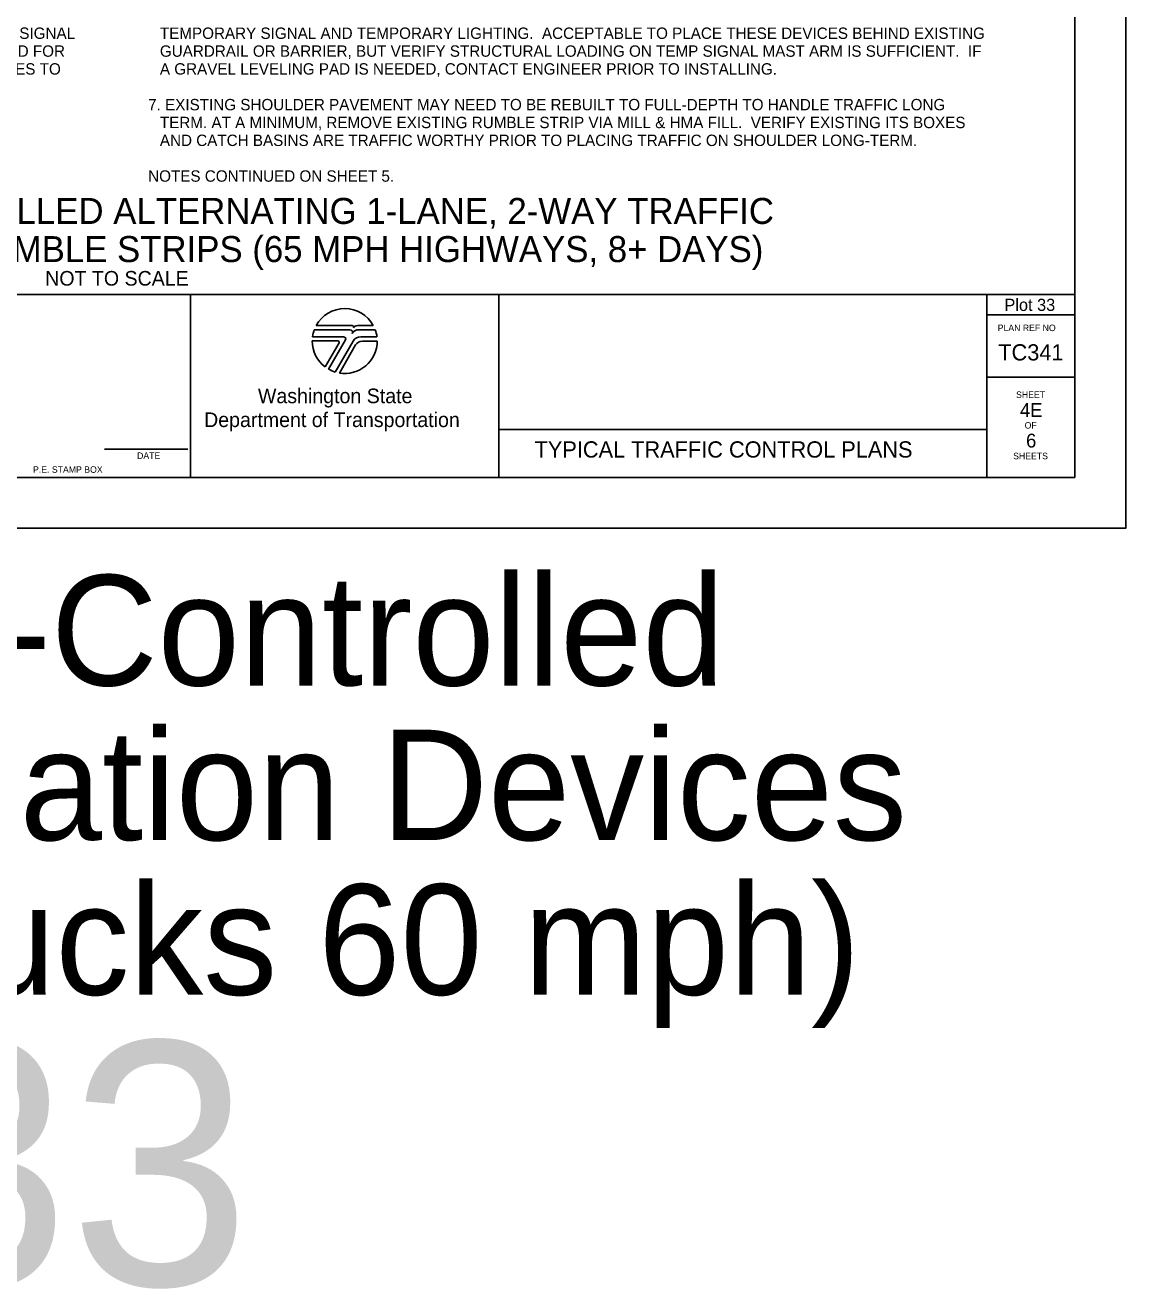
# Model space of a CAD drawing. Extents: x 99977 to 100176, y 99905 to 100011.
# Drawn here: x 100049.29 to 100056.06, y 99905.01 to 99912.78 of the extents above; entities that cross this region are included whole.
import ezdxf

# ---------------------------------------------------------------- set-up
doc = ezdxf.new("R2010")
doc.units = 0
for name, color, linetype in [('SH_DE_DetailHeading1Text', 7, 'Continuous'), ('SH_GI_GeneralNotesBodyText', 7, 'Continuous'), ('SH_GI_PlotLimits', 7, 'Continuous'), ('SH_GI_SheetBorder', 7, 'Continuous'), ('SH_GI_SheetLocationText', 7, 'Continuous'), ('SH_GI_SheetTextInCells', 7, 'Continuous'), ('SH_GI_TitleBlockText', 7, 'Continuous'), ('SH_GI_WSDOTLogo', 7, 'Continuous')]:
    doc.layers.add(name, color=color, linetype=linetype)

msp = doc.modelspace()

# ---------------------------------------------------------------- linework, layer by layer
at = {"layer": 'SH_GI_PlotLimits'}
msp.add_lwpolyline([(100039.0625, 99909.6875), (100056.0625, 99909.6875), (100056.0625, 99920.6875), (100039.0625, 99920.6875)], close=True, dxfattribs=at)
at = {"layer": 'SH_GI_SheetBorder'}
for p, q in [((100055.75, 99920.375), (100055.75, 99910)), ((100040, 99911.1259), (100055.75, 99911.1259)), ((100050.3089, 99911.1259), (100050.3089, 99910)), ((100052.2055, 99911.1259), (100052.2055, 99910)), ((100055.2079, 99911.1259), (100055.2079, 99910)), ((100055.2079, 99911.0008), (100055.75, 99911.0008)), ((100055.2079, 99910.6176), (100055.75, 99910.6176)), ((100052.2055, 99910.2955), (100055.2079, 99910.2955)), ((100049.7797, 99910.1733), (100050.2914, 99910.1733)), ((100040, 99910), (100055.75, 99910))]:
    msp.add_line(p, q, dxfattribs=at)
at = {"layer": 'SH_GI_WSDOTLogo'}
for p, q in [((100051.303, 99910.9354), (100051.0815, 99910.9354)), ((100051.433, 99910.9354), (100051.3351, 99910.9354)), ((100051.0572, 99910.84), (100051.2148, 99910.84)), ((100051.059, 99910.8661), (100051.2496, 99910.8661)), ((100051.2894, 99910.9094), (100051.0697, 99910.9094)), ((100051.261, 99910.8464), (100051.1567, 99910.6672)), ((100051.1989, 99910.6487), (100051.3089, 99910.839)), ((100051.343, 99910.9094), (100051.3429, 99910.9094)), ((100051.4448, 99910.9094), (100051.343, 99910.9094)), ((100051.3558, 99910.8661), (100051.4555, 99910.8661)), ((100051.3655, 99910.8394), (100051.4572, 99910.8394)), ((100051.222, 99910.8277), (100051.1364, 99910.6807)), ((100051.2244, 99910.6428), (100051.3242, 99910.8156))]:
    msp.add_line(p, q, dxfattribs=at)
for centre, radius, start, end in [((100051.2572, 99910.84), 0.2, 28.47865, 151.53204), ((100051.303, 99910.9263), 0.00903, 329.87418, 90.00328), ((100051.3352, 99910.9066), 0.0287, 90.00721, 148.16763), ((100051.2572, 99910.84), 0.2, 179.99864, 232.84327), ((100051.2572, 99910.84), 0.2, 159.69598, 172.50569), ((100051.2149, 99910.8318), 0.0082, 329.74356, 90), ((100051.2572, 99910.84), 0.2, 260.54554, 359.80857), ((100051.2497, 99910.853), 0.0131, 329.76834, 90), ((100051.2894, 99910.8946), 0.0148, 327.8418, 89.99855), ((100051.3429, 99910.861), 0.0484, 89.99529, 147.82376), ((100051.3558, 99910.8119), 0.0542, 90, 149.99738), ((100051.3654, 99910.7918), 0.0476, 90, 150.05432), ((100051.2572, 99910.84), 0.2, 7.49431, 20.29406), ((100051.2572, 99910.84), 0.2, 239.79292, 253.0448)]:
    msp.add_arc(centre, radius, start, end, dxfattribs=at)

# ---------------------------------------------------------------- texts
at = {"layer": 'SH_DE_DetailHeading1Text'}
for s, height, p in [('SIMPLE TEMPORARY SIGNAL-CONTROLLED ALTERNATING 1-LANE, 2-WAY TRAFFIC', 0.16, (100045.196, 99911.5606)), ('25 WZSL + CHANNELIZING DEVICES + RUMBLE STRIPS (65 MPH HIGHWAYS, 8+ DAYS)', 0.16, (100044.9338, 99911.3259)), ('NOT TO SCALE', 0.09, (100049.4141, 99911.1809))]:
    msp.add_text(s, height=height, rotation=360, dxfattribs=at).set_placement(p)
at = {"layer": 'SH_GI_GeneralNotesBodyText'}
for s, p in [(' THIS SIGNAL ', (100048.9894, 99912.6998)), ('TEMPORARY SIGNAL AND TEMPORARY LIGHTING.  ACCEPTABLE TO PLACE THESE DEVICES BEHIND EXISTING ', (100050.1197, 99912.6998)), ('  THE SIGNAL IS TIMED FOR ', (100048.272, 99912.5899)), ('GUARDRAIL OR BARRIER, BUT VERIFY STRUCTURAL LOADING ON TEMP SIGNAL MAST ARM IS SUFFICIENT.  IF ', (100050.1197, 99912.5899)), (' TO ALLOW BICYCLES TO ', (100048.3553, 99912.48)), ('A GRAVEL LEVELING PAD IS NEEDED, CONTACT ENGINEER PRIOR TO INSTALLING.', (100050.1197, 99912.48)), ('7. EXISTING SHOULDER PAVEMENT MAY NEED TO BE REBUILT TO FULL-DEPTH TO HANDLE TRAFFIC LONG ', (100050.0475, 99912.2602)), ('TERM. AT A MINIMUM, REMOVE EXISTING RUMBLE STRIP VIA MILL & HMA FILL.  VERIFY EXISTING ITS BOXES ', (100050.1197, 99912.1503)), ('AND CATCH BASINS ARE TRAFFIC WORTHY PRIOR TO PLACING TRAFFIC ON SHOULDER LONG-TERM.', (100050.1197, 99912.0404)), ('NOTES CONTINUED ON SHEET 5.', (100050.0475, 99911.8206))]:
    msp.add_text(s, height=0.07, rotation=360, dxfattribs=at).set_placement(p)
at = {"layer": 'SH_GI_SheetBorder'}
msp.add_text('PLAN REF NO', height=0.040032, dxfattribs=at).set_placement((100055.2747, 99910.9008))
at = {"layer": 'SH_GI_SheetLocationText'}
for s, height, p in [('Plot 33', 0.075, (100055.3164, 99911.025)), (' Temp Signal-Controlled', 0.68, (100043.7893, 99908.7191)), ('Alt Traffic w/ Channelization Devices', 0.68, (100039.9592, 99907.7671)), ('& Rumble Strips (65, Trucks 60 mph)', 0.68, (100039.4717, 99906.8151)), ('Plot 33', 1.5, (100044.4341, 99905.0267))]:
    msp.add_text(s, height=height, dxfattribs=at).set_placement(p)
at = {"layer": 'SH_GI_SheetTextInCells'}
for s, height, p in [('Washington State', 0.090072, (100050.7229, 99910.4571)), ('SHEET', 0.04003, (100055.3877, 99910.4896)), ('Department of Transportation', 0.090072, (100050.3916, 99910.3101)), ('OF', 0.04003, (100055.4406, 99910.3008)), ('DATE', 0.04003, (100049.9794, 99910.1141)), ('SHEETS', 0.04003, (100055.3698, 99910.112)), ('P.E. STAMP BOX', 0.040032, (100049.339, 99910.0286))]:
    msp.add_text(s, height=height, dxfattribs=at).set_placement(p)
at = {"layer": 'SH_GI_TitleBlockText'}
for s, height, p in [('TC341', 0.1, (100055.2784, 99910.72)), ('4E', 0.085, (100055.4116, 99910.3723)), ('TYPICAL TRAFFIC CONTROL PLANS', 0.1, (100052.4251, 99910.1224)), ('6', 0.085, (100055.4493, 99910.1843))]:
    msp.add_text(s, height=height, dxfattribs=at).set_placement(p)

doc.saveas('drawing.dxf')
